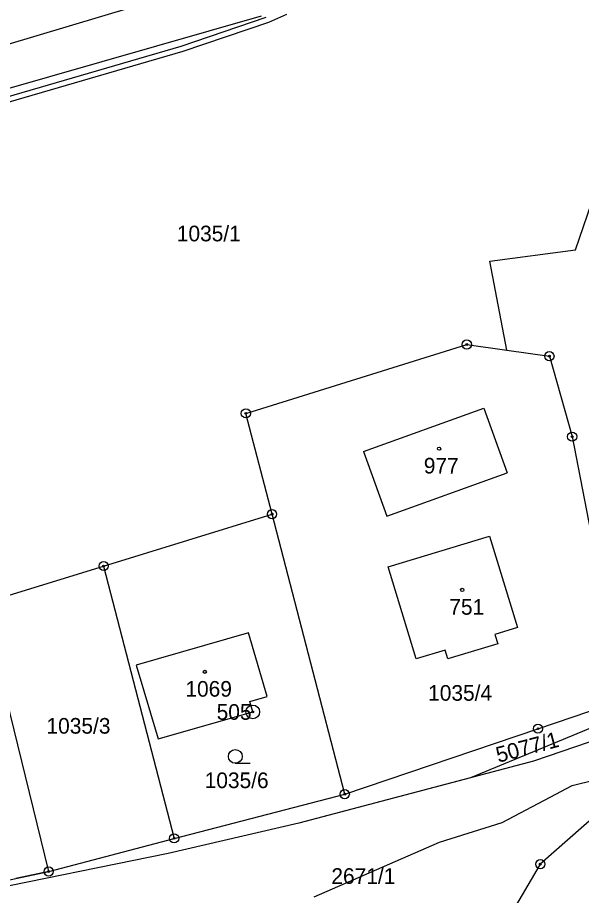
# Model space of a CAD drawing. Extents: x -439246 to -433691, y -1130252 to -1121148.
# Drawn here: x -438131.3 to -438070.1, y -1124216.2 to -1124120.8 of the extents above; entities that cross this region are included whole.
import ezdxf

# ---------------------------------------------------------------- set-up
doc = ezdxf.new("R2010")
doc.units = 0
for name, color, linetype in [('Vrstva 1', 7, 'Continuous'), ('Vrstva 16', 7, 'Continuous'), ('Vrstva 17', 7, 'Continuous'), ('Vrstva 18', 7, 'Continuous'), ('Vrstva 19', 7, 'Continuous'), ('Vrstva 24', 7, 'Continuous'), ('Vrstva 25', 7, 'Continuous'), ('Vrstva 3', 7, 'Continuous'), ('Vrstva 30', 7, 'Continuous'), ('Vrstva 37', 7, 'Continuous'), ('Vrstva 52', 7, 'Continuous')]:
    doc.layers.add(name, color=color, linetype=linetype)

msp = doc.modelspace()

# ---------------------------------------------------------------- linework, layer by layer
at = {"layer": 'Vrstva 1'}
msp.add_line((-438153.78, -1124134.66), (-438104.84, -1124120.64), dxfattribs=at)
for points in [[(-438156.61, -1124130.94), (-438098.32, -1124113.49)], [(-438070.71, -1124146.05), (-438065.51, -1124130.95)], [(-438080.02, -1124147.3), (-438070.71, -1124146.05)], [(-438078.15, -1124156.98), (-438080.02, -1124147.3)], [(-438106.52, -1124163.84), (-438082.52, -1124156.36)], [(-438082.52, -1124156.36), (-438078.15, -1124156.98)], [(-438078.15, -1124156.98), (-438073.54, -1124157.63)], [(-438073.54, -1124157.63), (-438071.07, -1124166.37)], [(-438093.75, -1124167.97), (-438080.67, -1124163.27)], [(-438080.67, -1124163.27), (-438078.13, -1124170.32)], [(-438103.68, -1124174.8), (-438106.52, -1124163.84)], [(-438071.07, -1124166.37), (-438065.51, -1124194.98)], [(-438093.75, -1124167.97), (-438091.21, -1124175.03)], [(-438091.21, -1124175.03), (-438078.13, -1124170.32)], [(-438121.98, -1124180.44), (-438103.68, -1124174.8)], [(-438095.78, -1124205.24), (-438103.68, -1124174.8)], [(-438091.06, -1124180.54), (-438080.06, -1124177.18)], [(-438080.06, -1124177.18), (-438077.02, -1124187.13)], [(-438135.09, -1124184.48), (-438121.98, -1124180.44)], [(-438121.98, -1124180.44), (-438114.32, -1124210.04)], [(-438088.01, -1124190.53), (-438091.06, -1124180.54)], [(-438127.95, -1124213.64), (-438135.09, -1124184.48)], [(-438077.02, -1124187.13), (-438079.46, -1124187.87)], [(-438106.23, -1124187.69), (-438118.43, -1124191.21)], [(-438104.22, -1124194.62), (-438106.23, -1124187.69)], [(-438079.46, -1124187.87), (-438079.16, -1124188.88)], [(-438079.16, -1124188.88), (-438084.56, -1124190.52)], [(-438084.85, -1124189.57), (-438088.01, -1124190.53)], [(-438084.56, -1124190.52), (-438084.85, -1124189.57)], [(-438118.43, -1124191.21), (-438116.04, -1124199.24)], [(-438106.1, -1124195.16), (-438104.22, -1124194.62)], [(-438105.78, -1124196.28), (-438106.1, -1124195.16)], [(-438074.78, -1124198.12), (-438065.51, -1124194.98)], [(-438116.04, -1124199.24), (-438105.78, -1124196.28)], [(-438095.78, -1124205.24), (-438074.78, -1124198.12)], [(-438067.72, -1124199.06), (-438075.27, -1124201.65)], [(-438075.27, -1124201.65), (-438100.75, -1124208.4)], [(-438114.32, -1124210.04), (-438095.78, -1124205.24)], [(-438068.33, -1124207.36), (-438074.53, -1124212.85)], [(-438100.75, -1124208.4), (-438114.97, -1124211.7)], [(-438127.95, -1124213.64), (-438114.32, -1124210.04)], [(-438114.97, -1124211.7), (-438135.97, -1124215.97)], [(-438074.53, -1124212.85), (-438080.78, -1124223.47)], [(-438127.95, -1124213.64), (-438131.51, -1124214.42)]]:
    msp.add_lwpolyline(points, dxfattribs=at)
at = {"layer": 'Vrstva 24'}
for centre, radius in [((-438082.52, -1124156.36), 0.5), ((-438082.52, -1124156.36), 0.1), ((-438073.54, -1124157.63), 0.5), ((-438073.54, -1124157.63), 0.1), ((-438106.52, -1124163.84), 0.5), ((-438106.52, -1124163.84), 0.1), ((-438071.07, -1124166.37), 0.5), ((-438071.07, -1124166.37), 0.1), ((-438103.68, -1124174.8), 0.5), ((-438103.68, -1124174.8), 0.1), ((-438121.98, -1124180.44), 0.5), ((-438121.98, -1124180.44), 0.1), ((-438105.78, -1124196.3), 0.75), ((-438105.78, -1124196.3), 0.1), ((-438074.78, -1124198.12), 0.5), ((-438074.78, -1124198.12), 0.1), ((-438095.78, -1124205.24), 0.5), ((-438095.78, -1124205.24), 0.1), ((-438114.32, -1124210.04), 0.5), ((-438114.32, -1124210.04), 0.1), ((-438074.53, -1124212.85), 0.5), ((-438074.53, -1124212.85), 0.1), ((-438127.95, -1124213.64), 0.5), ((-438127.95, -1124213.64), 0.1)]:
    msp.add_circle(centre, radius, dxfattribs=at)
at = {"layer": 'Vrstva 25'}
msp.add_line((-438107.67, -1124201.88), (-438106.07, -1124201.88), dxfattribs=at)
for centre, radius in [((-438085.53, -1124167.68), 0.175), ((-438083.01, -1124183.03), 0.175), ((-438110.98, -1124191.94), 0.175), ((-438107.67, -1124201.13), 0.75)]:
    msp.add_circle(centre, radius, dxfattribs=at)
at = {"layer": 'Vrstva 3'}
for points in [[(-438093.75, -1124167.97), (-438080.67, -1124163.27)], [(-438080.67, -1124163.27), (-438078.13, -1124170.32)], [(-438093.75, -1124167.97), (-438091.21, -1124175.03)], [(-438091.21, -1124175.03), (-438078.13, -1124170.32)], [(-438091.06, -1124180.54), (-438080.06, -1124177.18)], [(-438080.06, -1124177.18), (-438077.02, -1124187.13)], [(-438088.01, -1124190.53), (-438091.06, -1124180.54)], [(-438077.02, -1124187.13), (-438079.46, -1124187.87)], [(-438106.23, -1124187.69), (-438118.43, -1124191.21)], [(-438104.22, -1124194.62), (-438106.23, -1124187.69)], [(-438079.46, -1124187.87), (-438079.16, -1124188.88)], [(-438079.16, -1124188.88), (-438084.56, -1124190.52)], [(-438084.85, -1124189.57), (-438088.01, -1124190.53)], [(-438084.56, -1124190.52), (-438084.85, -1124189.57)], [(-438118.43, -1124191.21), (-438116.04, -1124199.24)], [(-438106.1, -1124195.16), (-438104.22, -1124194.62)], [(-438105.78, -1124196.28), (-438106.1, -1124195.16)], [(-438116.04, -1124199.24), (-438105.78, -1124196.28)]]:
    msp.add_lwpolyline(points, dxfattribs=at)
at = {"layer": 'Vrstva 30'}
for points in [[(-438132.58, -1124129.47), (-438113.54, -1124123.93), (-438104.3, -1124120.78)], [(-438102.11, -1124120.48), (-438104.08, -1124121.34), (-438113.36, -1124124.51), (-438132.4, -1124130.05)], [(-438022.38, -1124181.07), (-438038.49, -1124186.84), (-438049.98, -1124190.15), (-438082.11, -1124203.46), (-438100.75, -1124208.4), (-438114.97, -1124211.7), (-438135.97, -1124215.97), (-438152.44, -1124219.18), (-438172.51, -1124222.34), (-438177.48, -1124222.75), (-438171.25, -1124221.5), (-438165.02, -1124220.25), (-438154.18, -1124219.31), (-438150.01, -1124218.41), (-438131.51, -1124214.42), (-438127.95, -1124213.64), (-438114.32, -1124210.04), (-438095.78, -1124205.24), (-438074.78, -1124198.12), (-438065.51, -1124194.98), (-438061.85, -1124193.74), (-438055.48, -1124191.41)]]:
    msp.add_lwpolyline(points, dxfattribs=at)
at = {"layer": 'Vrstva 37'}
for centre in [(-438085.53, -1124167.68), (-438083.01, -1124183.03), (-438110.98, -1124191.94)]:
    msp.add_circle(centre, 0.175, dxfattribs=at)
at = {"layer": 'Vrstva 52'}
msp.add_lwpolyline([(-438099.09, -1124216.4), (-438085.49, -1124210.45), (-438078.69, -1124208.33), (-438073.46, -1124205.56), (-438071.05, -1124204.29), (-438065.94, -1124203.01), (-438051.5, -1124197.07), (-438042.15, -1124191.97), (-438038.75, -1124191.33), (-438033.65, -1124188.78), (-438025.15, -1124186.02), (-438003.91, -1124176.88), (-437998.76, -1124173.66), (-437997.1, -1124172.63), (-437988.61, -1124170.29), (-437983.51, -1124166.68), (-437982.03, -1124165.98), (-437975.86, -1124163.07), (-437971.61, -1124159.88)], dxfattribs=at)

# ---------------------------------------------------------------- texts
at = {"layer": 'Vrstva 16'}
msp.add_text('2671/1', height=1.7, dxfattribs=at).set_placement((-438097.232, -1124214.99))
at = {"layer": 'Vrstva 17'}
msp.add_text('505', height=1.7, dxfattribs=at).set_placement((-438109.698, -1124197.15))
at = {"layer": 'Vrstva 18'}
for s, p in [('1035/1', (-438114.025, -1124145.14)), ('1035/4', (-438086.718, -1124195.08)), ('1035/3', (-438128.188, -1124198.66)), ('1035/6', (-438111, -1124204.58))]:
    msp.add_text(s, height=1.7, dxfattribs=at).set_placement(p)
msp.add_text('5077/1', height=1.7, rotation=14.83758, dxfattribs=at).set_placement((-438079.087, -1124201.834))
at = {"layer": 'Vrstva 19'}
for s, p in [('977', (-438087.187, -1124170.38)), ('751', (-438084.419, -1124185.73)), ('1069', (-438113.094, -1124194.64))]:
    msp.add_text(s, height=1.7, dxfattribs=at).set_placement(p)

doc.saveas('drawing.dxf')
